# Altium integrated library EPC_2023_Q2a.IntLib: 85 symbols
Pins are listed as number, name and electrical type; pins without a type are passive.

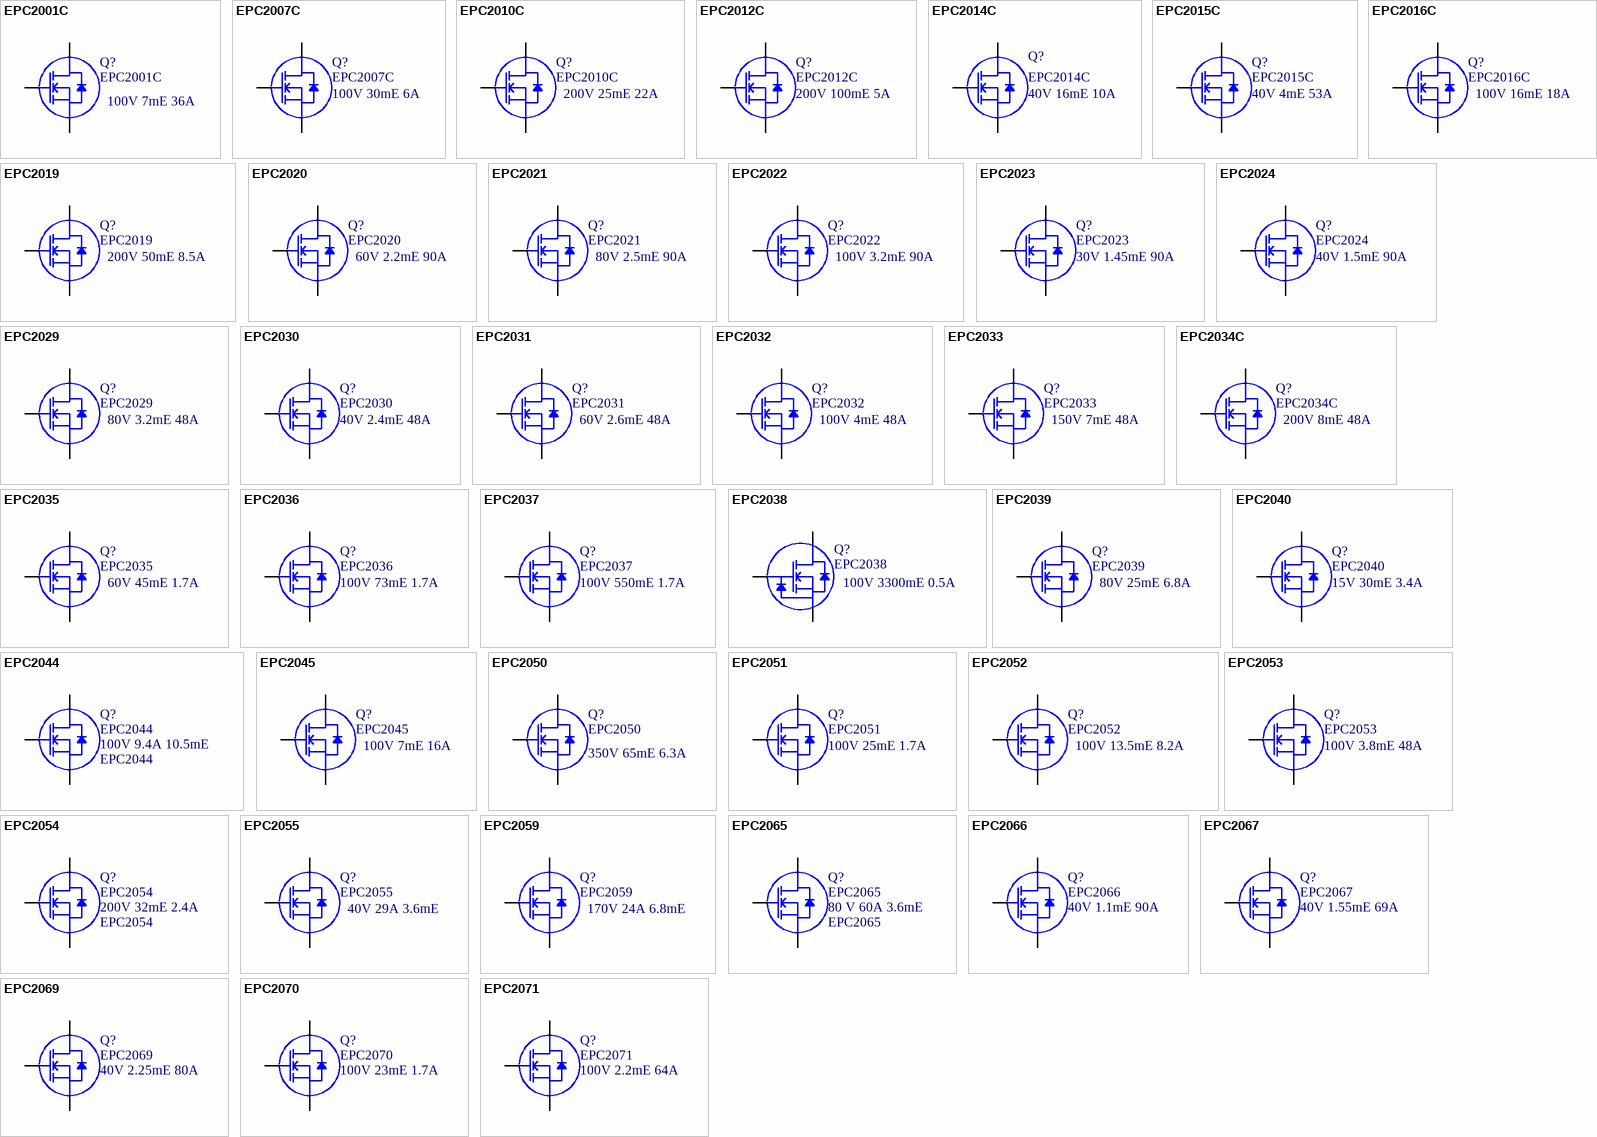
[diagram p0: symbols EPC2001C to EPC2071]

## EPC2001C
designator Q?
100V 7mE 36A; MFG: EPC
footprint D0188
pins: 1 G, 2 Sub (oe), 3 D1 (oc), 4 S1 (oe), 5 D2 (oc), 6 S2 (oe), 7 D3 (oc), 8 S3 (oe), 9 D4 (oc), 10 S4 (oe), 11 D5 (oc)

## EPC2007C
designator Q?
100V 30mE 6A; MFG: EPC
footprint D0199
pins: 1 G, 2 Sub (oe), 3 D1 (oc), 4 S1 (oe), 5 D2 (oc)

## EPC2010C
designator Q?
200V 25mE 22A; MFG: EPC
footprint D0309
pins: 1 G, 2 Sub (oe), 3 D1 (oc), 4 S1 (oe), 5 D2 (oc), 6 S2 (oe), 7 D3 (oc)

## EPC2012C
designator Q?
200V 100mE 5A; MFG: EPC
footprint D0375
pins: 1 G, 2 Sub (oe), 3 D (oc), 4 S (oe)

## EPC2014C
designator Q?
40V 16mE 10A; MFG: EPC
footprint D0199
pins: 1 G, 2 Sub (oe), 3 D1 (oc), 4 S1 (oe), 5 D2 (oc)

## EPC2015C
designator Q?
40V 4mE 53A; MFG: EPC
footprint D0188
pins: 1 G, 2 Sub (oe), 3 D1 (oc), 4 S1 (oe), 5 D2 (oc), 6 S2 (oe), 7 D3 (oc), 8 S3 (oe), 9 D4 (oc), 10 S4 (oe), 11 D5 (oc)

## EPC2016C
designator Q?
100V 16mE 18A; MFG: EPC
footprint D0155
pins: 1 G, 2 Sub (oe), 3 D1 (oc), 4 SP1 (oe), 5 D2 (oc), 6 SP2 (oe)

## EPC2019
designator Q?
200V 50mE 8.5A; MFG: EPC
footprint D0364
pins: 1 G, 2 S3 (oe), 3 D1 (oc), 4 S1 (oe), 5 D2 (oc), 6 S2 (oe), 7 Sub (oe)

## EPC2020
designator Q?
60V 2.2mE 90A; MFG: EPC
footprint D0232
pins: 1 G, 2 S1 (oe), 3 D1 (oc), 4 D1 (oc), 5 S2 (oe), 6 S3 (oe), 7 D2 (oc), 8 D3 (oc), 9 S4 (oe), 10 S5 (oe), 11 D4 (oc), 12 D5 (oc), 13 S6 (oe), 14 S7 (oe), 15 D6 (oc), 16 D7 (oc), 17 S8 (oe), 18 S9 (oe), 19 D8 (oc), 20 D9 (oc), 21 S10 (oe), 22 S11 (oe), 23 D10 (oc), 24 D11 (oc), 25 S12 (oe), 26 S13 (oe), 27 D12 (oc), 28 D13 (oc), 29 S14 (oe), 30 Sub (oe)

## EPC2021
designator Q?
80V 2.5mE 90A; MFG: EPC
footprint D0232
pins: 1 G, 2 S1 (oe), 3 D1 (oc), 4 D2 (oc), 5 S2 (oe), 6 S3 (oe), 7 D3 (oc), 8 D4 (oc), 9 S4 (oe), 10 S5 (oe), 11 D5 (oc), 12 D6 (oc), 13 S6 (oe), 14 S7 (oe), 15 D7 (oc), 16 D8 (oc), 17 S8 (oe), 18 S9 (oe), 19 D9 (oc), 20 D10 (oc), 21 S10 (oe), 22 S11 (oe), 23 D11 (oc), 24 D12 (oc), 25 S12 (oe), 26 S13 (oe), 27 D13 (oc), 28 D14 (oc), 29 S14 (oe), 30 Sub (oe)

## EPC2022
designator Q?
100V 3.2mE 90A; MFG: EPC
footprint D0232
pins: 1 G, 2 S1 (oe), 3 D1 (oc), 4 D2 (oc), 5 S2 (oe), 6 S3 (oe), 7 D3 (oc), 8 D4 (oc), 9 S4 (oe), 10 S5 (oe), 11 D5 (oc), 12 D6 (oc), 13 S6 (oe), 14 S7 (oe), 15 D7 (oc), 16 D8 (oc), 17 S8 (oe), 18 S9 (oe), 19 D9 (oc), 20 D10 (oc), 21 S10 (oe), 22 S11 (oe), 23 D11 (oc), 24 D12 (oc), 25 S12 (oe), 26 S13 (oe), 27 D13 (oc), 28 D14 (oc), 29 S14 (oe), 30 Sub (oe)

## EPC2023
designator Q?
30V 1.45mE 90A; MFG: EPC
footprint D0232
pins: 1 G, 2 S1 (oe), 3 D1 (oc), 4 D2 (oc), 5 S2 (oe), 6 S3 (oe), 7 D3 (oc), 8 D4 (oc), 9 S4 (oe), 10 S5 (oe), 11 D5 (oc), 12 D6 (oc), 13 S6 (oe), 14 S7 (oe), 15 D7 (oc), 16 D8 (oc), 17 S8 (oe), 18 S9 (oe), 19 D9 (oc), 20 D10 (oc), 21 S10 (oe), 22 S11 (oe), 23 D11 (oc), 24 D12 (oc), 25 S12 (oe), 26 S13 (oe), 27 D13 (oc), 28 D14 (oc), 29 S14 (oe), 30 Sub (oe)

## EPC2024
designator Q?
40V 1.5mE 90A; MFG: EPC
footprint D0232
pins: 1 G, 2 S1 (oe), 3 D1 (oc), 4 D2 (oc), 5 S2 (oe), 6 S3 (oe), 7 D3 (oc), 8 D4 (oc), 9 S4 (oe), 10 S5 (oe), 11 D5 (oc), 12 D6 (oc), 13 S6 (oe), 14 S7 (oe), 15 D7 (oc), 16 D8 (oc), 17 S8 (oe), 18 S9 (oe), 19 D9 (oc), 20 D10 (oc), 21 S10 (oe), 22 S11 (oe), 23 D11 (oc), 24 D12 (oc), 25 S12 (oe), 26 S13 (oe), 27 D13 (oc), 28 D14 (oc), 29 S14 (oe), 30 Sub (oe)

## EPC2029
designator Q?
80V 3.2mE 48A; MFG: EPC
footprint D0386T3
footprint D0386T4
pins: 1 G, 2 G, 3 S1 (oe), 4 S2 (oe), 5 D1 (oc), 6 D2 (oc), 7 D3 (oc), 8 D4 (oc), 9 D5 (oc), 10 S3 (oe), 11 S4 (oe), 12 Sub (oe), 13 S5 (oe), 14 S6 (oe), 15 D6 (oc), 16 D7 (oc), 17 D8 (oc), 18 D9 (oc), 19 D10 (oc), 20 S7 (oe), 21 S8 (oe), 22 S9 (oe), 23 S10 (oe), 24 S11 (oe)

## EPC2030
designator Q?
40V 2.4mE 48A; MFG: EPC
footprint D0386T3
footprint D0386T4
pins: 1 G, 2 G, 3 S1 (oe), 4 S2 (oe), 5 D1 (oc), 6 D2 (oc), 7 D3 (oc), 8 D4 (oc), 9 D5 (oc), 10 S3 (oe), 11 S4 (oe), 12 Sub (oe), 13 S5 (oe), 14 S6 (oe), 15 D6 (oc), 16 D7 (oc), 17 D8 (oc), 18 D9 (oc), 19 D10 (oc), 20 S7 (oe), 21 S8 (oe), 22 S9 (oe), 23 S10 (oe), 24 S11 (oe)

## EPC2031
designator Q?
60V 2.6mE 48A; MFG: EPC
footprint D0386T3
footprint D0386T4
pins: 1 G, 2 G, 3 S1 (oe), 4 S2 (oe), 5 D1 (oc), 6 D2 (oc), 7 D3 (oc), 8 D4 (oc), 9 D5 (oc), 10 S3 (oe), 11 S4 (oe), 12 Sub (oe), 13 S5 (oe), 14 S6 (oe), 15 D6 (oc), 16 D7 (oc), 17 D8 (oc), 18 D9 (oc), 19 D10 (oc), 20 S7 (oe), 21 S8 (oe), 22 S9 (oe), 23 S10 (oe), 24 S11 (oe)

## EPC2032
designator Q?
100V 4mE 48A; MFG: EPC
footprint D0386T3
footprint D0386T4
pins: 1 G, 2 G, 3 S1 (oe), 4 S2 (oe), 5 D1 (oc), 6 D2 (oc), 7 D3 (oc), 8 D4 (oc), 9 D5 (oc), 10 S3 (oe), 11 S4 (oe), 12 Sub (oe), 13 S5 (oe), 14 S6 (oe), 15 D6 (oc), 16 D7 (oc), 17 D8 (oc), 18 D9 (oc), 19 D10 (oc), 20 S7 (oe), 21 S8 (oe), 22 S9 (oe), 23 S10 (oe), 24 S11 (oe)

## EPC2033
designator Q?
150V 7mE 48A; MFG: EPC
footprint D0386T3
footprint D0386T4
pins: 1 G, 2 G, 3 S1 (oe), 4 S2 (oe), 5 D1 (oc), 6 D2 (oc), 7 D3 (oc), 8 D4 (oc), 9 D5 (oc), 10 S3 (oe), 11 S4 (oe), 12 Sub (oe), 13 S5 (oe), 14 S6 (oe), 15 D6 (oc), 16 D7 (oc), 17 D8 (oc), 18 D9 (oc), 19 D10 (oc), 20 S7 (oe), 21 S8 (oe), 22 S9 (oe), 23 S10 (oe), 24 S11 (oe)

## EPC2034C
designator Q?
200V 8mE 48A; MFG: EPC
footprint D0386T3
footprint D0386T4
pins: 1 G, 2 G, 3 S1 (oe), 4 S2 (oe), 5 D1 (oc), 6 D2 (oc), 7 D3 (oc), 8 D4 (oc), 9 D5 (oc), 10 S3 (oe), 11 S4 (oe), 12 Sub (oe), 13 S5 (oe), 14 S6 (oe), 15 D6 (oc), 16 D7 (oc), 17 D8 (oc), 18 D9 (oc), 19 D10 (oc), 20 S7 (oe), 21 S8 (oe), 22 S9 (oe), 23 S10 (oe), 24 S11 (oe)

## EPC2035
designator Q?
60V 45mE 1.7A; MFG: EPC
footprint D0353
pins: 1 G, 2 S1 (oe), 3 D1 (oc), 4 S2 (oe)

## EPC2036
designator Q?
100V 73mE 1.7A; MFG: EPC
footprint D0353
pins: 1 G, 2 S1 (oe), 3 D1 (oc), 4 S2 (oe)

## EPC2037
designator Q?
100V 550mE 1.7A; MFG: EPC
footprint D0353
pins: 1 G, 2 S1 (oe), 3 D1 (oc), 4 S2 (oe)

## EPC2038
designator Q?
100V 3300mE 0.5A; MFG: EPC
footprint D0353
pins: 1 G, 2 S1 (oe), 3 D1 (oc), 4 S2 (oe)

## EPC2039
designator Q?
80V 25mE 6.8A; MFG: EPC
footprint D0144
pins: 1 G, 2 S1 (oe), 3 S2 (oe), 4 D1 (oc), 5 D2 (oc), 6 D3 (oc), 7 D4 (oc), 8 S3 (oe), 9 S4 (oe)

## EPC2040
designator Q?
15V 30mE 3.4A; MFG: EPC
footprint D0210
pins: 1 G, 2 D1 (oc), 3 S1 (oe), 4 S2 (oe), 5 D2 (oc), 6 S3 (oe)

## EPC2044
designator Q?  SchDescript: 100V 9.4A 10.5mE
100V 10.5mE 9.4A; MFG: EPC; Name: Dahlia
footprint D0265
pins: A1 G, A2 D1 (oc), A3 S3 (oe), A4 D4 (oc), A5 S6 (oe), B1 S1 (oe), B2 D2 (oc), B3 S4 (oe), B4 D5 (oc), B5 S7 (oe), C1 S2 (oe), C2 D3 (oc), C3 S5 (oe), C4 D6 (oc), C5 S8 (oe)

## EPC2045
designator Q?
100V 7mE 16A; MFG: EPC
footprint D0012
pins: 1 G, 2 S1 (oe), 3 S2 (oe), 4 D1 (oc), 5 D2 (oc), 6 D3 (oc), 7 S3 (oe), 8 Sub (oe), 9 S4 (oe), 10 D4 (oc), 11 D5 (oc), 12 D6 (oc), 13 S5 (oe), 14 S6 (oe), 15 S7 (oe)

## EPC2050
designator Q?
350V 65mE 6.3A; MFG: EPC
footprint D0078
pins: 1 G, 2 S1 (oe), 3 S2 (oe), 4 S3 (oe), 5 D1 (oc), 6 D2 (oc), 7 D3 (oc), 8 D4 (oc), 9 S4 (oe), 10 S5 (oe), 11 Sub (oe), 12 S6 (oe)

## EPC2051
designator Q?
100V 25mE 1.7A; MFG: EPC
footprint D0001
pins: 1 G, 2 S1 (oe), 3 D1 (oc), 4 D2 (oc), 5 S2 (oe), 6 Sub (oe)

## EPC2052
designator Q?
100V 13.5mE 8.2A; MFG: EPC
footprint D0045
pins: 1 G, 2 S1 (oe), 3 S2 (oe), 4 D1 (oc), 5 D2 (oc), 6 D3 (oc), 7 S3 (oe), 8 S5 (oe), 9 S4 (oe)

## EPC2053
designator Q?
100V 3.8mE 48A; MFG: EPC
footprint D0034
pins: 1 G, 2 S1 (oe), 3 S2 (oe), 4 S3 (oe), 5 D1 (oc), 6 D2 (oc), 7 D3 (oc), 8 D4 (oc), 9 S4 (oe), 10 S5 (oe), 11 S6 (oe), 12 S7 (oe), 13 D5 (oc), 14 D6 (oc), 15 D7 (oc), 16 D8 (oc), 17 S8 (oe), 18 S9 (oe), 19 S10 (oe), 20 S11 (oe), 21 D9 (oc), 22 D10 (oc), 23 D11 (oc), 24 D12 (oc), 25 S12 (oe), 26 S13 (oe), 27 S14 (oe), 28 S15 (oe)

## EPC2054
designator Q?
200V 32mE 2.4A; MFG: EPC
footprint D0474
pins: 1 G, 2 S1 (oe), 3 D (oc), 4 S2 (oe)

## EPC2055
designator Q?
40V 29A 3.6mE; MFG: EPC
footprint D0133CT44M
pins: 1 G, 2 S (oe), 3 D (oc), 4 S (oe), 5 D (oc), 6 S (oe)

## EPC2059
designator Q?  SchDescript: 170V 24A 6.8mE
170V 25A 9mE; MFG: EPC
footprint D0298T34M
pins: 1 G, 2 S, 3 D, 4 S, 5 D, 6 S

## EPC2065
designator Q?
80 V 60A 3.6mE; MFG: EPC
footprint D0320T34M
pins: 1 G, 2 S, 3 D, 4 S, 5 D, 6 S, 7 D, 8 S

## EPC2066
designator Q?
40V 1.1mE 90A; MFG: EPC; Name: Aspen
footprint D0650
footprint D0232
pins: 1 G, 2 S1 (oe), 3 D1 (oc), 4 D2 (oc), 5 S2 (oe), 6 S3 (oe), 7 D3 (oc), 8 D4 (oc), 9 S4 (oe), 10 S5 (oe), 11 D5 (oc), 12 D6 (oc), 13 S6 (oe), 14 S7 (oe), 15 D7 (oc), 16 D8 (oc), 17 S8 (oe), 18 S9 (oe), 19 D9 (oc), 20 D10 (oc), 21 S10 (oe), 22 S11 (oe), 23 D11 (oc), 24 D12 (oc), 25 S12 (oe), 26 S13 (oe), 27 D13 (oc), 28 D14 (oc), 29 S14 (oe), 30 Sub (oe)

## EPC2067
designator Q?
40V 1.55mE 69A; MFG: EPC
footprint D0540
pins: 1 G, 2 S1 (oe), 3 D1 (oc), 4 D2 (oc), 5 S2 (oe), 6 S3 (oe), 7 D3 (oc), 8 D4 (oc), 9 S4 (oe), 10 S5 (oe), 11 D5 (oc), 12 D6 (oc), 13 S6 (oe), 14 S7 (oe)

## EPC2069
designator Q?  SchDescript: 40V 2.25mE 80A
40V 2.25mE 69A; MFG: EPC; Name: Charon
footprint D0496
pins: 1 G, 2 S1 (oe), 3 D1 (oc), 4 D2 (oc), 5 S2 (oe), 6 S3 (oe), 7 D3 (oc), 8 D4 (oc), 9 S4 (oe), 10 S5 (oe), 11 D5 (oc), 12 D6 (oc), 13 S6 (oe), 14 S7 (oe), 15 D7 (oc), 16 D8 (oc)

## EPC2070
designator Q?
100V 23mE 1.7A; MFG: EPC; Name: Cedar
footprint D0562AT4
pins: 1 G, 2 S1 (oe), 3 D1 (oc), 4 D2 (oc), 5 S2 (oe), 6 Sub (oe)

## EPC2071
designator Q?
100V 2.2mE 64A; MFG: EPC; Name: Mahogany
footprint D0683
pins: 1 G, 2 S1 (oe), 3 D1 (oc), 4 D2 (oc), 5 S2 (oe), 6 S3 (oe), 7 D3 (oc), 8 D4 (oc), 9 S4 (oe), 10 S5 (oe), 11 D5 (oc), 12 D6 (oc), 13 S6 (oe), 14 S7 (oe), 15 D7 (oc), 16 D8 (oc), 17 S8 (oe), 18 S9 (oe), 19 D9 (oc), 20 D10 (oc), 21 S10 (oe), 22 S11 (oe)

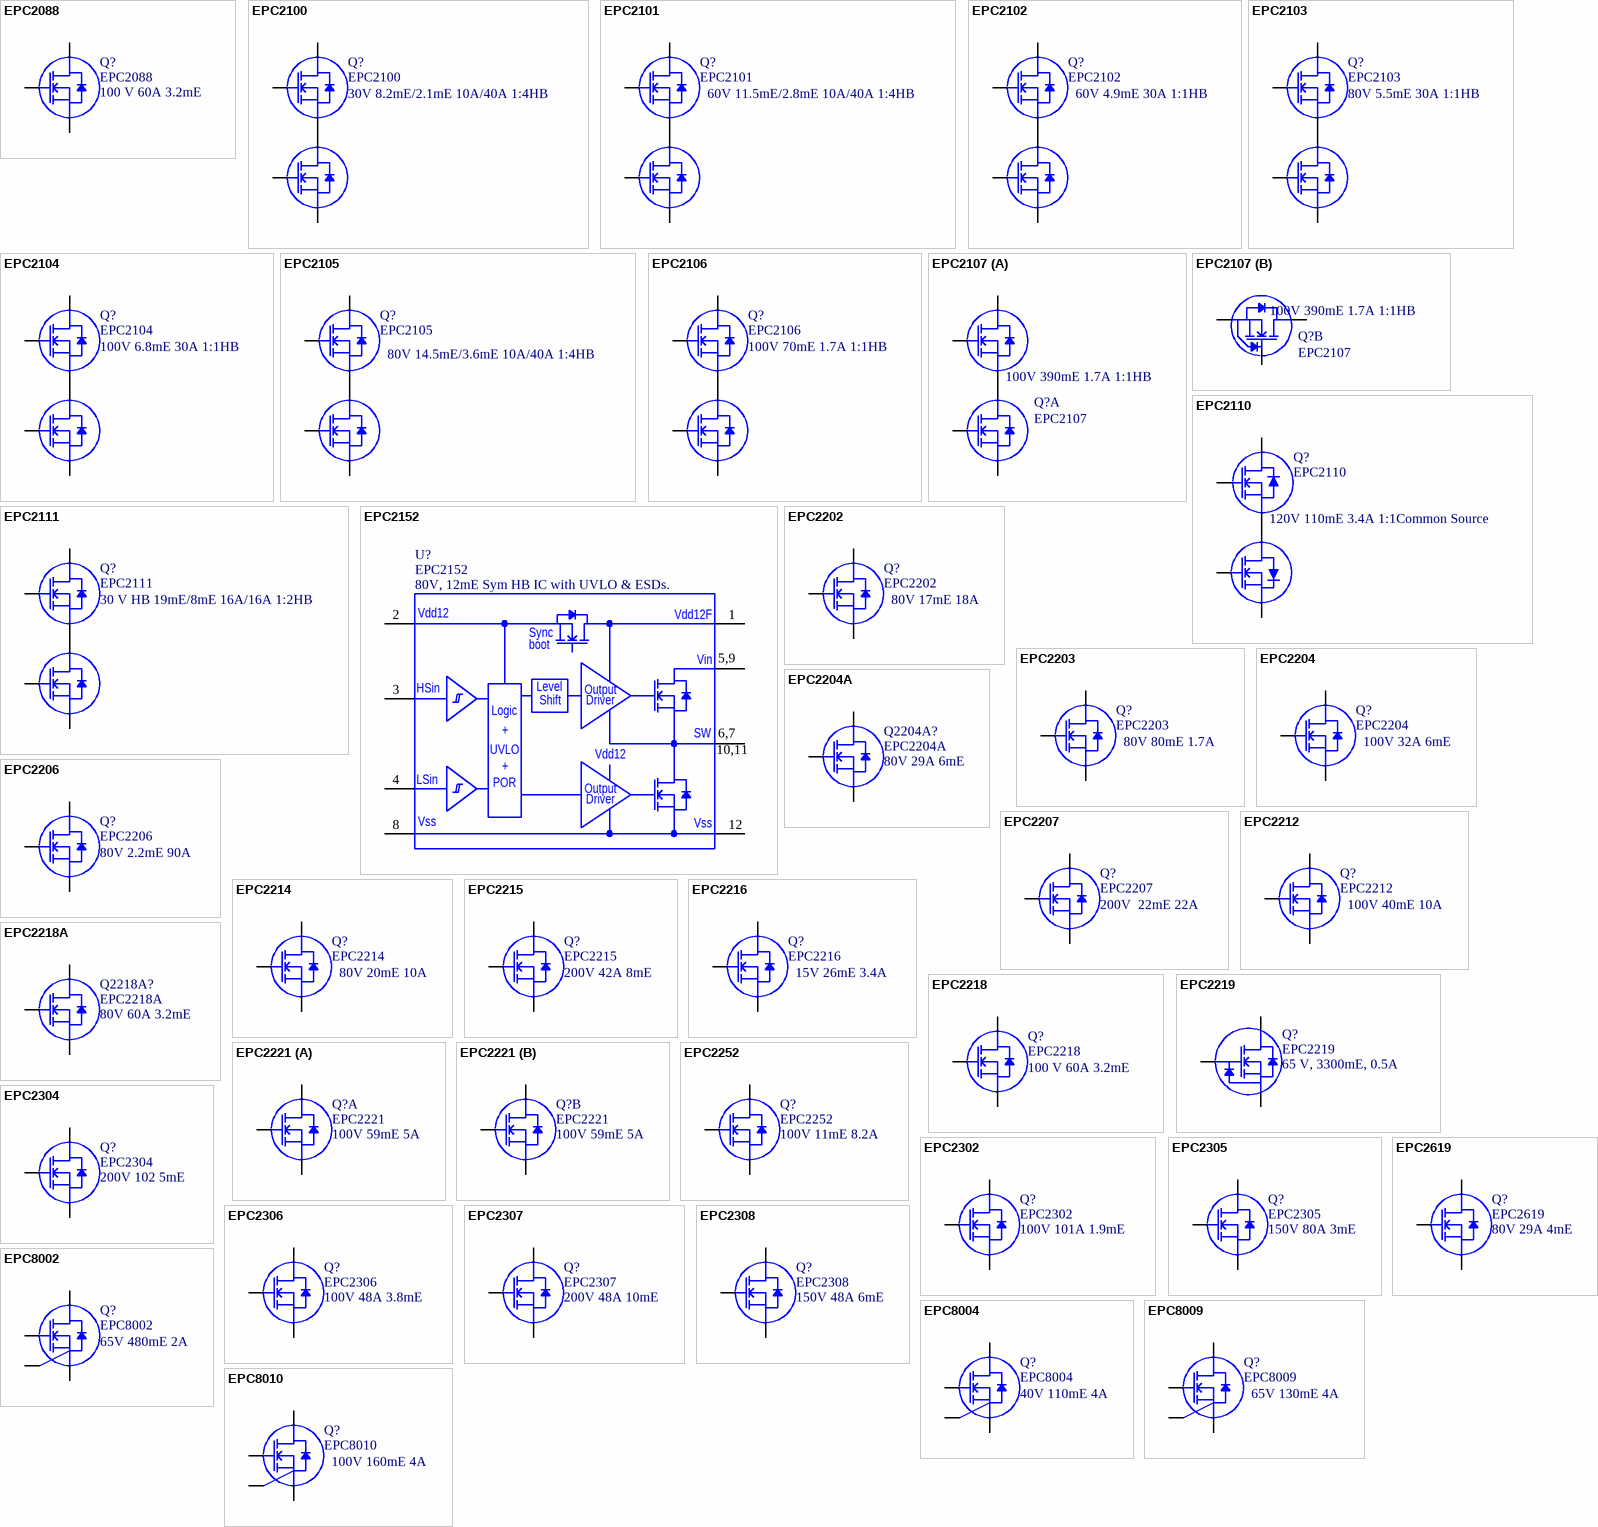
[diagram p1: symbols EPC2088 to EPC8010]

## EPC2088
designator Q?
100 V 60A 3.2mE; MFG: EPC
footprint D0320T34M
pins: 1 G, 2 S, 3 D, 4 S, 5 D, 6 S, 7 D, 8 S

## EPC2100
designator Q?
30V 8.2mE/2.1mE 10A/40A 1:4HB; MFG: EPC
footprint D0342
pins: 1 D1 (oc), 2 G1, 3 SG1, 4 G2, 5 S2 (oe), 6 S1 (oe), 7 D2 (oc), 8 D2 (oc), 9 D2 (oc), 10 D2 (oc), 11 D1 (oc), 12 S2 (oe), 13 S2 (oe), 14 S2 (oe), 15 S2 (oe), 16 S1 (oe), 17 D2 (oc), 18 D2 (oc), 19 D2 (oc), 20 D2 (oc), 21 D1 (oc), 22 S2 (oe), 23 S2 (oe), 24 S2 (oe), 25 S2 (oe), 26 S1 (oe), 27 D2 (oc), 28 D2 (oc), 29 D2 (oc), 30 D2 (oc), 31 D1 (oc), 32 S2 (oe), 33 S2 (oe), 34 S2 (oe), 35 S2 (oe), 36 S1 (oe), 37 D2 (oc), 38 D2 (oc), 39 D2 (oc), 40 D2 (oc), 41 D1 (oc), 42 S2 (oe), 43 S2 (oe), 44 S2 (oe), 45 S2 (oe), 46 S1 (oe), 47 D2 (oc), 48 D2 (oc), 49 D2 (oc), 50 D2 (oc), 51 D1 (oc), 52 S2 (oe), 53 S2 (oe), 54 S2 (oe), 55 S2 (oe), 56 S1 (oe), 57 D2 (oc), 58 D2 (oc), 59 D2 (oc), 60 D2 (oc), 61 D1 (oc), 62 S2 (oe), 63 S2 (oe), 64 S2 (oe), 65 S2 (oe), 66 S1 (oe), 67 D2 (oc), 68 D2 (oc), 69 D2 (oc), 70 D2 (oc), 71 D1 (oc), 72 S2 (oe), 73 S2 (oe), 74 S2 (oe), 75 S2 (oe)

## EPC2101
designator Q?
60V 11.5mE/2.8mE 10A/40A 1:4HB; MFG: EPC
footprint D0342
pins: 1 D1 (oc), 2 G1, 3 SG1, 4 G2, 5 S2 (oe), 6 S1 (oe), 7 D2 (oc), 8 D2 (oc), 9 D2 (oc), 10 D2 (oc), 11 D1 (oc), 12 S2 (oe), 13 S2 (oe), 14 S2 (oe), 15 S2 (oe), 16 S1 (oe), 17 D2 (oc), 18 D2 (oc), 19 D2 (oc), 20 D2 (oc), 21 D1 (oc), 22 S2 (oe), 23 S2 (oe), 24 S2 (oe), 25 S2 (oe), 26 S1 (oe), 27 D2 (oc), 28 D2 (oc), 29 D2 (oc), 30 D2 (oc), 31 D1 (oc), 32 S2 (oe), 33 S2 (oe), 34 S2 (oe), 35 S2 (oe), 36 S1 (oe), 37 D2 (oc), 38 D2 (oc), 39 D2 (oc), 40 D2 (oc), 41 D1 (oc), 42 S2 (oe), 43 S2 (oe), 44 S2 (oe), 45 S2 (oe), 46 S1 (oe), 47 D2 (oc), 48 D2 (oc), 49 D2 (oc), 50 D2 (oc), 51 D1 (oc), 52 S2 (oe), 53 S2 (oe), 54 S2 (oe), 55 S2 (oe), 56 S1 (oe), 57 D2 (oc), 58 D2 (oc), 59 D2 (oc), 60 D2 (oc), 61 D1 (oc), 62 S2 (oe), 63 S2 (oe), 64 S2 (oe), 65 S2 (oe), 66 S1 (oe), 67 D2 (oc), 68 D2 (oc), 69 D2 (oc), 70 D2 (oc), 71 D1 (oc), 72 S2 (oe), 73 S2 (oe), 74 S2 (oe), 75 S2 (oe)

## EPC2102
designator Q?
60V 4.9mE 30A 1:1HB; MFG: EPC
footprint D0342
pins: 1 D1 (oc), 2 G1, 3 SG1, 4 G2, 5 S2 (oe), 6 S1 (oe), 7 S1 (oc), 8 S1 (oc), 9 D2 (oc), 10 D2 (oc), 11 D1 (oc), 12 D1 (oe), 13 D1 (oe), 14 S2 (oe), 15 S2 (oe), 16 S1 (oe), 17 S1 (oc), 18 S1 (oc), 19 D2 (oc), 20 D2 (oc), 21 D1 (oc), 22 D1 (oe), 23 D1 (oe), 24 S2 (oe), 25 S2 (oe), 26 S1 (oe), 27 S1 (oc), 28 S1 (oc), 29 D2 (oc), 30 D2 (oc), 31 D1 (oc), 32 D1 (oe), 33 D1 (oe), 34 S2 (oe), 35 S2 (oe), 36 S1 (oe), 37 S1 (oc), 38 S1 (oc), 39 D2 (oc), 40 D2 (oc), 41 D1 (oc), 42 D1 (oe), 43 S2 (oe), 44 S2 (oe), 45 S2 (oe), 46 S1 (oe), 47 S1 (oc), 48 S1 (oc), 49 D2 (oc), 50 D2 (oc), 51 D1 (oc), 52 D1 (oe), 53 S2 (oe), 54 S2 (oe), 55 S2 (oe), 56 S1 (oe), 57 S1 (oc), 58 S1 (oc), 59 D2 (oc), 60 D2 (oc), 61 D1 (oc), 62 D1 (oe), 63 S2 (oe), 64 S2 (oe), 65 S2 (oe), 66 S1 (oe), 67 S1 (oc), 68 S1 (oc), 69 D2 (oc), 70 D2 (oc), 71 D1 (oc), 72 D1 (oe), 73 S2 (oe), 74 S2 (oe), 75 S2 (oe)

## EPC2103
designator Q?
80V 5.5mE 30A 1:1HB; MFG: EPC
footprint D0342
pins: 1 D1 (oc), 2 G1, 3 SG1, 4 G2, 5 S2 (oe), 6 S1 (oe), 7 S1 (oc), 8 S1 (oc), 9 D2 (oc), 10 D2 (oc), 11 D1 (oc), 12 D1 (oe), 13 D1 (oe), 14 S2 (oe), 15 S2 (oe), 16 S1 (oe), 17 S1 (oc), 18 S1 (oc), 19 D2 (oc), 20 D2 (oc), 21 D1 (oc), 22 D1 (oe), 23 D1 (oe), 24 S2 (oe), 25 S2 (oe), 26 S1 (oe), 27 S1 (oc), 28 S1 (oc), 29 D2 (oc), 30 D2 (oc), 31 D1 (oc), 32 D1 (oe), 33 D1 (oe), 34 S2 (oe), 35 S2 (oe), 36 S1 (oe), 37 S1 (oc), 38 S1 (oc), 39 D2 (oc), 40 D2 (oc), 41 D1 (oc), 42 D1 (oe), 43 S2 (oe), 44 S2 (oe), 45 S2 (oe), 46 S1 (oe), 47 S1 (oc), 48 S1 (oc), 49 D2 (oc), 50 D2 (oc), 51 D1 (oc), 52 D1 (oe), 53 S2 (oe), 54 S2 (oe), 55 S2 (oe), 56 S1 (oe), 57 S1 (oc), 58 S1 (oc), 59 D2 (oc), 60 D2 (oc), 61 D1 (oc), 62 D1 (oe), 63 S2 (oe), 64 S2 (oe), 65 S2 (oe), 66 S1 (oe), 67 S1 (oc), 68 S1 (oc), 69 D2 (oc), 70 D2 (oc), 71 D1 (oc), 72 D1 (oe), 73 S2 (oe), 74 S2 (oe), 75 S2 (oe)

## EPC2104
designator Q?
100V 6.8mE 30A 1:1HB; MFG: EPC
footprint D0342
pins: 1 D1 (oc), 2 G1, 3 SG1, 4 G2, 5 S2 (oe), 6 S1 (oe), 7 S1 (oc), 8 S1 (oc), 9 D2 (oc), 10 D2 (oc), 11 D1 (oc), 12 D1 (oe), 13 D1 (oe), 14 S2 (oe), 15 S2 (oe), 16 S1 (oe), 17 S1 (oc), 18 S1 (oc), 19 D2 (oc), 20 D2 (oc), 21 D1 (oc), 22 D1 (oe), 23 D1 (oe), 24 S2 (oe), 25 S2 (oe), 26 S1 (oe), 27 S1 (oc), 28 S1 (oc), 29 D2 (oc), 30 D2 (oc), 31 D1 (oc), 32 D1 (oe), 33 D1 (oe), 34 S2 (oe), 35 S2 (oe), 36 S1 (oe), 37 S1 (oc), 38 S1 (oc), 39 D2 (oc), 40 D2 (oc), 41 D1 (oc), 42 D1 (oe), 43 S2 (oe), 44 S2 (oe), 45 S2 (oe), 46 S1 (oe), 47 S1 (oc), 48 S1 (oc), 49 D2 (oc), 50 D2 (oc), 51 D1 (oc), 52 D1 (oe), 53 S2 (oe), 54 S2 (oe), 55 S2 (oe), 56 S1 (oe), 57 S1 (oc), 58 S1 (oc), 59 D2 (oc), 60 D2 (oc), 61 D1 (oc), 62 D1 (oe), 63 S2 (oe), 64 S2 (oe), 65 S2 (oe), 66 S1 (oe), 67 S1 (oc), 68 S1 (oc), 69 D2 (oc), 70 D2 (oc), 71 D1 (oc), 72 D1 (oe), 73 S2 (oe), 74 S2 (oe), 75 S2 (oe)

## EPC2105
designator Q?
80V 14.5mE/3.6mE 10A/40A 1:4HB; MFG: EPC
footprint D0342
pins: 1 D1 (oc), 2 G1, 3 SG1, 4 G2, 5 S2 (oe), 6 S1 (oe), 7 D2 (oc), 8 D2 (oc), 9 D2 (oc), 10 D2 (oc), 11 D1 (oc), 12 S2 (oe), 13 S2 (oe), 14 S2 (oe), 15 S2 (oe), 16 S1 (oe), 17 D2 (oc), 18 D2 (oc), 19 D2 (oc), 20 D2 (oc), 21 D1 (oc), 22 S2 (oe), 23 S2 (oe), 24 S2 (oe), 25 S2 (oe), 26 S1 (oe), 27 D2 (oc), 28 D2 (oc), 29 D2 (oc), 30 D2 (oc), 31 D1 (oc), 32 S2 (oe), 33 S2 (oe), 34 S2 (oe), 35 S2 (oe), 36 S1 (oe), 37 D2 (oc), 38 D2 (oc), 39 D2 (oc), 40 D2 (oc), 41 D1 (oc), 42 S2 (oe), 43 S2 (oe), 44 S2 (oe), 45 S2 (oe), 46 S1 (oe), 47 D2 (oc), 48 D2 (oc), 49 D2 (oc), 50 D2 (oc), 51 D1 (oc), 52 S2 (oe), 53 S2 (oe), 54 S2 (oe), 55 S2 (oe), 56 S1 (oe), 57 D2 (oc), 58 D2 (oc), 59 D2 (oc), 60 D2 (oc), 61 D1 (oc), 62 S2 (oe), 63 S2 (oe), 64 S2 (oe), 65 S2 (oe), 66 S1 (oe), 67 D2 (oc), 68 D2 (oc), 69 D2 (oc), 70 D2 (oc), 71 D1 (oc), 72 S2 (oe), 73 S2 (oe), 74 S2 (oe), 75 S2 (oe)

## EPC2106
designator Q?
100V 70mE 1.7A 1:1HB; MFG: EPC
footprint D0144
pins: 1 G1, 2 S1 (oe), 3 G2, 4 D1 (oc), 5 S1 (oe), 6 S2 (oe), 7 D1 (oc), 8 D2 (oc), 9 S2 (oe)

## EPC2107
designator Q?
100V 390mE 1.7A 1:1HB; MFG: EPC
footprint D0144
part A pins: 1 G1, 2 G2 (oc), 4 S1 (oe), 5 D2 (oe), 7 D1 (oe), 8 S2 (oe)
part B pins: 3 G3 (oe), 6 D3 (oc), 9 S3

## EPC2110
designator Q?
120V 110mE 3.4A 1:1Common Source; MFG: EPC
footprint D0144
pins: 1 G1, 2 D1 (oe), 3 D1 (oe), 4 S (oc), 5 S (oe), 6 S (oe), 7 G2, 8 D2 (oc), 9 D2 (oc)

## EPC2111
designator Q?
30 V HB 19mE/8mE 16A/16A 1:2HB; MFG: EPC
footprint D0331
pins: 1 G1 (power), 2 VSW1 (power), 3 G2, 4 VIN1 (power), 5 VSW2 (power), 6 GND1 (power), 7 VIN2 (power), 8 VSW3 (power), 9 GND2 (power), 10 VIN3 (power), 11 VSW4 (power), 12 GND3 (power), 13 VIN4 (power), 14 VSW5 (power), 15 GND4 (power), 16 VIN5 (power), 17 VSW6 (power), 18 GND5 (power), 19 VIN6 (power), 20 VSW7 (power), 21 GND6 (power)

## EPC2152
designator U?
80V, 12mE Sym HB IC with UVLO & ESDs.; MFG: EPC
footprint D0122
pins: 1 Vdd12F, 2 Vdd12, 3 HSin, 4 LSin, 5 Vin, 6 SW, 7 SW, 8 Vss, 9 Vin, 10 SW, 11 SW, 12 Vss

## EPC2202
designator Q?
80V 17mE 18A; MFG: EPC
footprint D0155
pins: 1 G, 2 Sub (oe), 3 D1 (oc), 4 SP1 (oe), 5 D2 (oc), 6 SP2 (oe)

## EPC2203
designator Q?
80V 80mE 1.7A; MFG: EPC
footprint D0353
pins: 1 G, 2 S1 (oe), 3 D1 (oc), 4 S2 (oe)

## EPC2204
designator Q?
100V 32A 6mE; MFG: EPC
footprint D0133CT44M
pins: 1 G, 2 S (oe), 3 D (oc), 4 S (oe), 5 D (oc), 6 S (oe)

## EPC2204A
designator Q2204A?
80V 29A 6mE; MFG: EPC; Name: Plumeria
footprint D0133CT44M
pins: 1 G, 2 S (oe), 3 D (oc), 4 S (oe), 5 D (oc), 6 S (oe)

## EPC2206
designator Q?
80V 2.2mE 90A; MFG: EPC
footprint D0232
pins: 1 G, 2 S1 (oe), 3 D1 (oc), 4 D2 (oc), 5 S2 (oe), 6 S3 (oe), 7 D3 (oc), 8 D4 (oc), 9 S4 (oe), 10 S5 (oe), 11 D5 (oc), 12 D6 (oc), 13 S6 (oe), 14 S7 (oe), 15 D7 (oc), 16 D8 (oc), 17 S8 (oe), 18 S9 (oe), 19 D9 (oc), 20 D10 (oc), 21 S10 (oe), 22 S11 (oe), 23 D11 (oc), 24 D12 (oc), 25 S12 (oe), 26 S13 (oe), 27 D13 (oc), 28 D14 (oc), 29 S14 (oe), 30 Sub (oe)

## EPC2207
designator Q?  SchDescript: 200V  22mE 22A
200V 13A 22mE; MFG: EPC
footprint D0177B
pins: 1 G, 2 S (oe), 3 D (oc), 4 S (oe), 5 D (oc), 6 S (oe)

## EPC2212
designator Q?
100V 40mE 10A; MFG: EPC
footprint D0155
pins: 1 G, 2 Sub (oe), 3 D1 (oc), 4 SP1 (oe), 5 D2 (oc), 6 SP2 (oe)

## EPC2214
designator Q?
80V 20mE 10A; MFG: EPC
footprint D0166
pins: 1 G, 2 S1 (oe), 3 S2 (oe), 4 D1 (oc), 5 D2 (oc), 6 D3 (oc), 7 D4 (oc), 8 S3 (oe), 9 S4 (oe)

## EPC2215
designator Q?
200V 42A 8mE; MFG: EPC
footprint D0111BT34M
pins: 1 G, 2 S, 3 D, 4 S, 5 D, 6 S

## EPC2216
designator Q?
15V 26mE 3.4A; MFG: EPC
footprint D0210
pins: 1 G, 2 D1 (oc), 3 S1 (oe), 4 S2 (oe), 5 D2 (oc), 6 S3 (oe)

## EPC2218
designator Q?
100 V 60A 3.2mE; MFG: EPC
footprint D0320T34M
pins: 1 G, 2 S, 3 D, 4 S, 5 D, 6 S, 7 D, 8 S

## EPC2218A
designator Q2218A?
80V 60A 3.2mE; MFG: EPC; Name: Hibiscus
footprint D0320T34M
pins: 1 G, 2 S, 3 D, 4 S, 5 D, 6 S, 7 D, 8 S

## EPC2219
designator Q?
65 V, 3300mE, 0.5A; MFG: EPC
footprint D0353
pins: 1 G, 2 S1 (oe), 3 D1 (oc), 4 S2 (oe)

## EPC2221
designator Q?
100V 59mE 5A; MFG: EPC; Name: Itachi
footprint D0551
part A pins: 1 G1, 2 D1a (oc), 3 D1b (oc), 4 S1a (oe), 6 S1b (oe)
part B pins: 5 S2 (oe), 7 G2, 8 D2a (oc), 9 D2b (oc)

## EPC2252
designator Q?
100V 11mE 8.2A; MFG: EPC; Name: Spruce
footprint D0045
pins: 1 G, 2 S1 (oe), 3 S2 (oe), 4 D1 (oc), 5 D2 (oc), 6 D3 (oc), 7 S3 (oe), 8 S5 (oe), 9 S4 (oe)

## EPC2302
designator Q?
100V 101A 1.9mE; MFG: EPC; Name: Bellini
footprint D0606F_100V
pins: 1 G, 2 S, 3 D, 4 S, 5 D, 6 S, 7 D

## EPC2304
designator Q?  SchDescript: 200V 102 5mE
200V 102A 5.0mE; MFG: EPC; Name: Mimosa
footprint D0606F_200V
pins: 1 G, 2 S, 3 D, 4 S, 5 D, 6 S, 7 D

## EPC2305
designator Q?  SchDescript: 150V 80A 3mE
150V 80A 3.0mE; MFG: EPC; Name: Spritz
footprint D0606F_200V
pins: 1 G, 2 S, 3 D, 4 S, 5 D, 6 S, 7 D

## EPC2306
designator Q?
100V 48A 3.8mE; MFG: EPC; Name: Rossini
footprint D0606H_100V
pins: 1 G, 2 S, 3 D, 4 S, 5 D, 6 S, 7 D

## EPC2307
designator Q?
200V 48A 10mE; MFG: EPC; Name: Sangria
footprint D0606H_200V
pins: 1 G, 2 S, 3 D, 4 S, 5 D, 6 S, 7 D

## EPC2308
designator Q?  SchDescript: 150V 48A 6mE
150V 48A 6.0mE; MFG: EPC; Name: Sidecar
footprint D0606H_200V
pins: 1 G, 2 S, 3 D, 4 S, 5 D, 6 S, 7 D

## EPC2619
designator Q?
80V 29A 4mE; MFG: EPC; Name: Excalibur
footprint D0133CT44M
pins: 1 G, 2 S (oe), 3 D (oc), 4 S (oe), 5 D (oc), 6 S (oe)

## EPC8002
designator Q?
65V 480mE 2A; MFG: EPC
footprint D0221
pins: 1 G, 2 SG (oe), 3 SP1 (oe), 4 D (oc), 5 SP2 (oe), 6 Sub (oe)

## EPC8004
designator Q?
40V 110mE 4A; MFG: EPC
footprint D0221
pins: 1 G, 2 SG (oe), 3 SP1 (oe), 4 D (oc), 5 SP2 (oe), 6 Sub (oe)

## EPC8009
designator Q?
65V 130mE 4A; MFG: EPC
footprint D0221
pins: 1 G, 2 SG (oe), 3 SP1 (oe), 4 D (oc), 5 SP2 (oe), 6 Sub (oe)

## EPC8010
designator Q?
100V 160mE 4A; MFG: EPC
footprint D0221
pins: 1 G, 2 SG (oe), 3 SP1 (oe), 4 D (oc), 5 SP2 (oe), 6 Sub (oe)

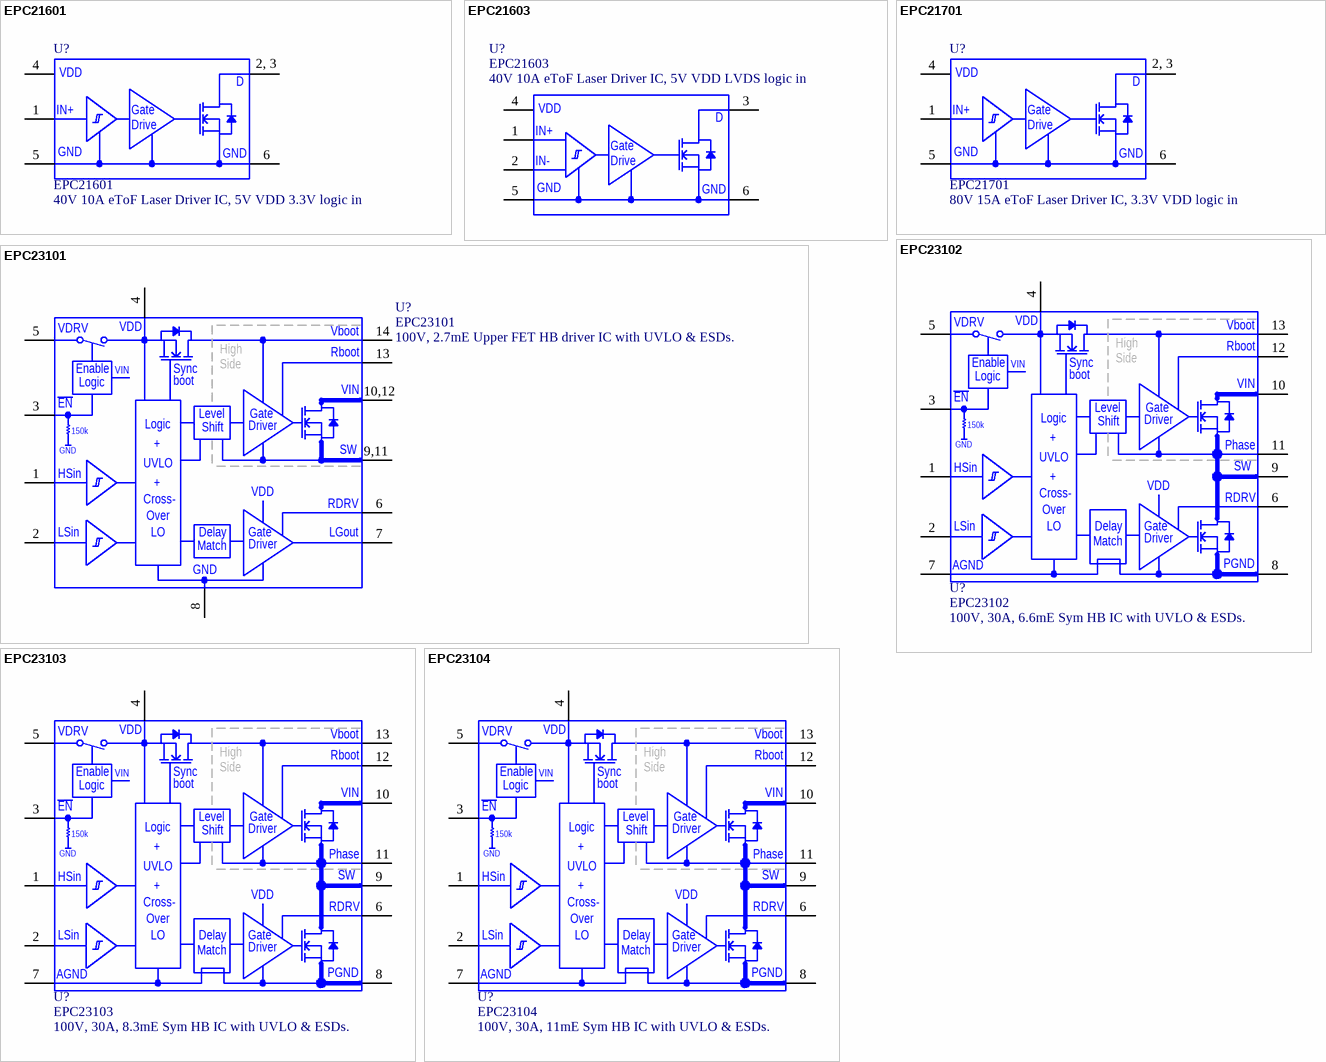
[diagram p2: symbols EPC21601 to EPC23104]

## EPC21601
designator U?  SchDescript: 40V 10A eToF Laser Driver IC, 5V VDD 3.3V logic in
eToF Laser Driver IC, 40V 10A with 5V VDD, 3.3V logic input; MFG: EPC
footprint D0452
pins: 1 IN+, 2 D, 3 D, 4 VDD, 5 GND, 6 GND

## EPC21603
designator U?  SchDescript: 40V 10A eToF Laser Driver IC, 5V VDD LVDS logic in  (hidden comment: EPC21603)
eToF Laser Driver IC, 40V 10A with 5V VDD, LVDS input; MFG: EPC
footprint D0452
pins: 1 IN+, 2 IN-, 3 D, 4 VDD, 5 GND, 6 GND

## EPC21701
designator U?  SchDescript: 80V 15A eToF Laser Driver IC, 3.3V VDD logic in
eToF Laser Driver IC, 80V 15A with 5V VDD, 3.3V logic input; MFG: EPC; Name: Eos
footprint D0617
pins: 1 IN+, 2 D, 3 D, 4 VDD, 5 GND, 6 GND

## EPC23101
designator U?  SchDescript: 100V, 2.7mE Upper FET HB driver IC with UVLO & ESDs.
80V, 2.7mE Upper FET HB driver IC with UVLO & ESDs.; MFG: EPC; Name: Chewbacca
footprint D0629
pins: 1 HSin, 2 LSin, 3 ENb, 4 VDD, 5 VDRV, 6 RDRV, 7 LGout, 8 GND, 9 SW, 10 VIN, 11 SW, 12 VIN, 13 Rboot, 14 Vboot
1 alternate drawing of the same symbol

## EPC23102
designator U?
100V, 30A, 6.6mE Sym HB IC with UVLO & ESDs.; MFG: EPC; Name: Kenobi
footprint D0727
pins: 1 HSin, 2 LSin, 3 ENb, 4 VDD, 5 VDRV, 6 RDRV, 7 AGND, 8 PGND, 9 SW, 10 VIN, 11 Phase, 12 Rboot, 13 Vboot
1 alternate drawing of the same symbol

## EPC23103
designator U?
100V, 30A, 8.3mE Sym HB IC with UVLO & ESDs.; MFG: EPC; Name: MiniKenobi
footprint D0727
pins: 1 HSin, 2 LSin, 3 ENb, 4 VDD, 5 VDRV, 6 RDRV, 7 AGND, 8 PGND, 9 SW, 10 VIN, 11 Phase, 12 Rboot, 13 Vboot
1 alternate drawing of the same symbol

## EPC23104
designator U?
100V, 30A, 11mE Sym HB IC with UVLO & ESDs.; MFG: EPC; Name: MicroKenobi
footprint D0727
pins: 1 HSin, 2 LSin, 3 ENb, 4 VDD, 5 VDRV, 6 RDRV, 7 AGND, 8 PGND, 9 SW, 10 VIN, 11 Phase, 12 Rboot, 13 Vboot
1 alternate drawing of the same symbol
